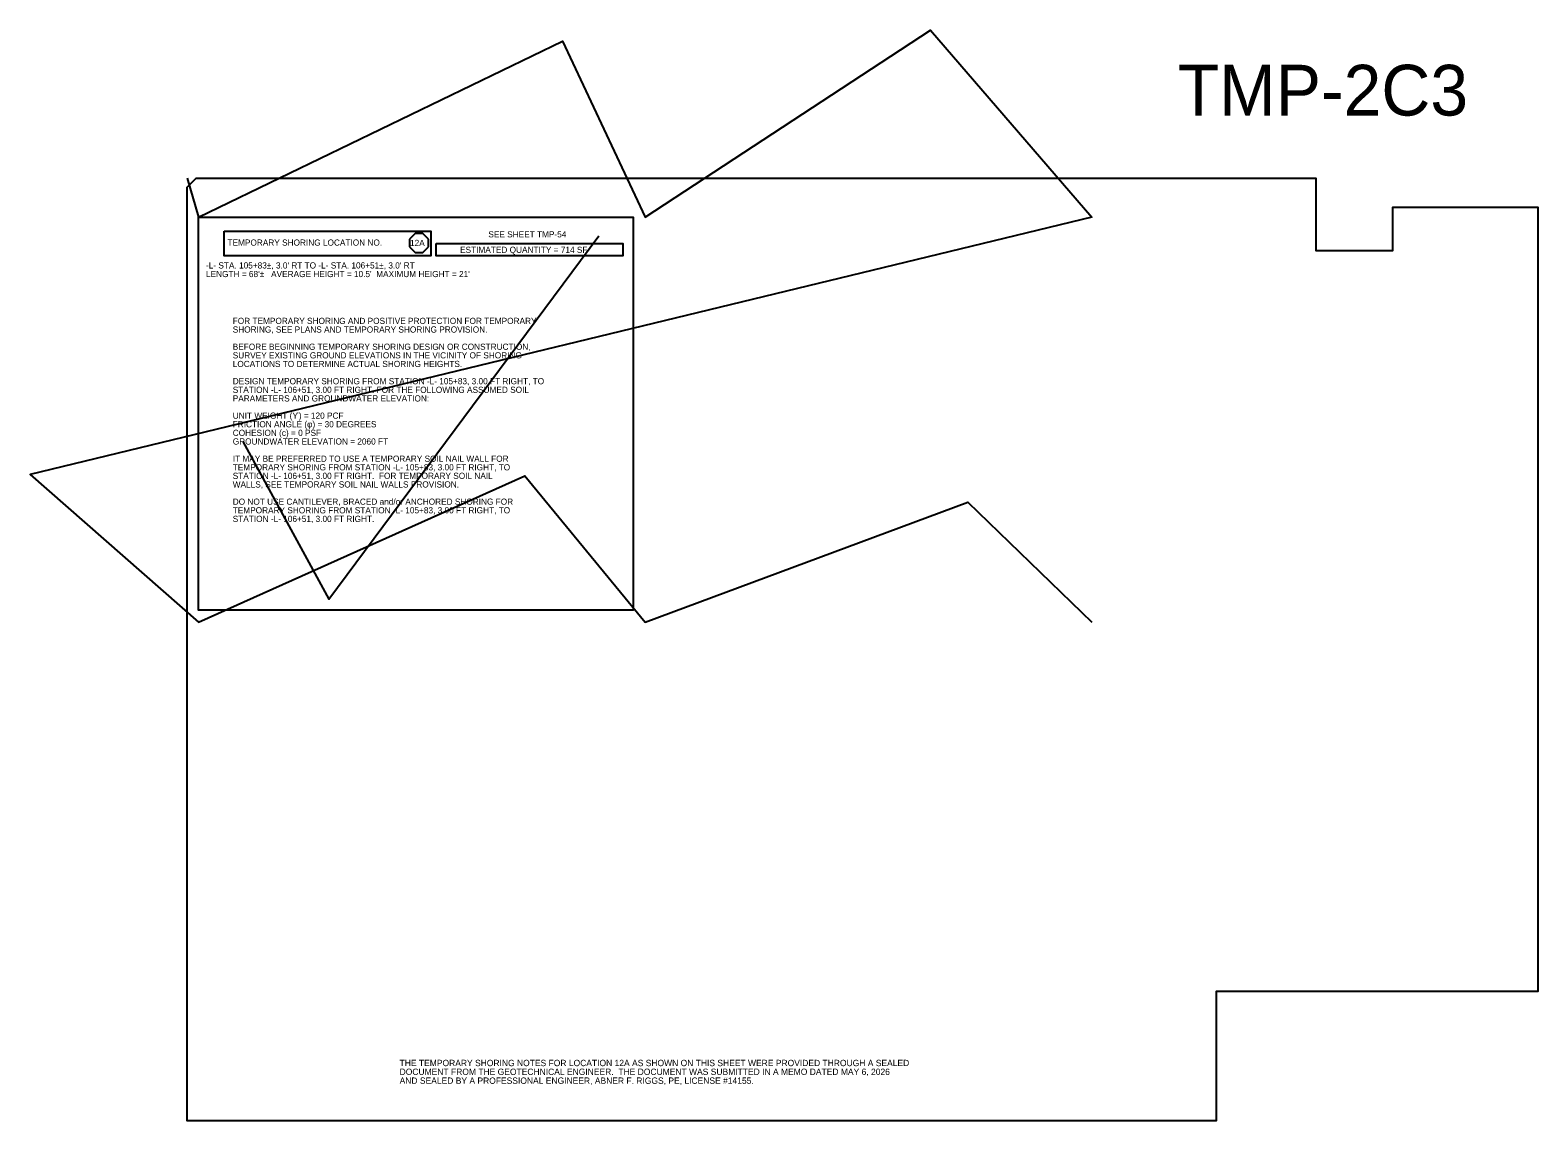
# Model space of a CAD drawing. Extents: x 2487012 to 2497594, y 369516 to 371986.
# Drawn here: x 2495931 to 2497594, y 370242 to 371445 of the extents above; entities that cross this region are included whole.
import ezdxf

# ---------------------------------------------------------------- set-up
doc = ezdxf.new("R2010")
doc.units = 0
for name, color, linetype in [('Scratch_Level_2', 7, 'Continuous'), ('Scratch_Level_3', 7, 'Continuous'), ('Scratch_Level_6', 7, 'Continuous'), ('TC LABEL TEMP SHORING', 7, 'Continuous'), ('TC SHEET BORDER LINE THIN', 7, 'Continuous'), ('TC SHEET LAYOUT SHAPE', 7, 'Continuous'), ('TC SHEET TEXT', 7, 'Continuous')]:
    doc.layers.add(name, color=color, linetype=linetype)

msp = doc.modelspace()

# ---------------------------------------------------------------- linework, layer by layer
at = {"layer": 'Scratch_Level_2'}
msp.add_lwpolyline([(2496165.7, 370991.6), (2496260.7, 370817.8), (2496558.3, 371218.6)], dxfattribs=at)
at = {"layer": 'Scratch_Level_3'}
msp.add_line((2496104.4, 371282.3), (2496104.4, 371282.3), dxfattribs=at)
at = {"layer": 'Scratch_Level_6'}
msp.add_lwpolyline([(2496104.4, 371282.3), (2496116.7, 371239.1), (2496518.3, 371433.4), (2496609.6, 371239.1), (2496924.4, 371445.4), (2497102.5, 371239.1), (2495931.1, 370955.2), (2496116.7, 370792.3), (2496477, 370953.9), (2496609.6, 370792.3), (2496965.7, 370924.6), (2497102.5, 370792.3)], dxfattribs=at)
at = {"layer": 'TC LABEL TEMP SHORING'}
for p, q in [((2496355.7, 371221.2), (2496349.6, 371215)), ((2496364.3, 371221.2), (2496355.7, 371221.2)), ((2496370.4, 371215), (2496364.3, 371221.2)), ((2496349.6, 371215), (2496349.6, 371206.3)), ((2496349.6, 371206.3), (2496355.7, 371200.1)), ((2496364.3, 371200.1), (2496370.4, 371206.3)), ((2496370.4, 371206.3), (2496370.4, 371215)), ((2496355.7, 371200.1), (2496364.3, 371200.1))]:
    msp.add_line(p, q, dxfattribs=at)
at = {"layer": 'TC SHEET BORDER LINE THIN'}
for points in [[(2496116.7, 371239.1), (2496596.2, 371239.1), (2496596.2, 370805.5), (2496116.7, 370805.5)], [(2496145.2, 371223.5), (2496373.3, 371223.5), (2496373.3, 371196.3), (2496145.2, 371196.3)], [(2496379, 371209.9), (2496584.8, 371209.9), (2496584.8, 371196.3), (2496379, 371196.3)]]:
    msp.add_lwpolyline(points, close=True, dxfattribs=at)
at = {"layer": 'TC SHEET LAYOUT SHAPE'}
msp.add_lwpolyline([(2496104.4, 370690.8), (2496104.4, 371000.2), (2496104.4, 371272.3), (2496114.4, 371282.3), (2496557.4, 371282.3), (2497028.4, 371282.3), (2497349.4, 371282.3), (2497349.4, 371202.3), (2497434.4, 371202.3), (2497434.4, 371250.3), (2497594.4, 371250.3), (2497594.4, 370915.3), (2497594.4, 370636.1), (2497594.4, 370384.8), (2497239.4, 370384.8), (2497239.4, 370242.3), (2496866.2, 370242.3), (2496696.8, 370242.3), (2496344, 370242.3), (2496104.4, 370242.3)], close=True, dxfattribs=at)

# ---------------------------------------------------------------- texts
at = {"layer": 'TC LABEL TEMP SHORING'}
msp.add_text('12A', height=6.81, dxfattribs=at).set_placement((2496350.2, 371207.3))
at = {"layer": 'TC SHEET BORDER LINE THIN'}
for s, p in [('SHORING, SEE PLANS AND TEMPORARY SHORING PROVISION.', (2496154.6, 371111.8)), ('FOR TEMPORARY SHORING AND POSITIVE PROTECTION FOR TEMPORARY ', (2496154.6, 371121.3)), ('SURVEY EXISTING GROUND ELEVATIONS IN THE VICINITY OF SHORING ', (2496154.6, 371083.3)), ('BEFORE BEGINNING TEMPORARY SHORING DESIGN OR CONSTRUCTION, ', (2496154.6, 371092.8)), ('LOCATIONS TO DETERMINE ACTUAL SHORING HEIGHTS.', (2496154.6, 371073.8)), ('STATION -L- 106+51, 3.00 FT RIGHT. FOR THE FOLLOWING ASSUMED SOIL ', (2496154.6, 371045.3)), ('DESIGN TEMPORARY SHORING FROM STATION -L- 105+83, 3.00 FT RIGHT, TO ', (2496154.6, 371054.8)), ('PARAMETERS AND GROUNDWATER ELEVATION:', (2496154.6, 371035.8)), ('UNIT WEIGHT (ϒ) = 120 PCF', (2496154.6, 371016.8)), ('COHESION (c) = 0 PSF', (2496154.6, 370997.8)), ('FRICTION ANGLE (φ) = 30 DEGREES', (2496154.6, 371007.3)), ('GROUNDWATER ELEVATION = 2060 FT', (2496154.6, 370988.3)), ('IT MAY BE PREFERRED TO USE A TEMPORARY SOIL NAIL WALL FOR', (2496154.6, 370969.3)), ('TEMPORARY SHORING FROM STATION -L- 105+83, 3.00 FT RIGHT, TO', (2496154.6, 370959.8)), ('STATION -L- 106+51, 3.00 FT RIGHT.  FOR TEMPORARY SOIL NAIL', (2496154.6, 370950.4)), ('WALLS, SEE TEMPORARY SOIL NAIL WALLS PROVISION.', (2496154.6, 370940.9)), ('TEMPORARY SHORING FROM STATION -L- 105+83, 3.00 FT RIGHT, TO', (2496154.6, 370912.4)), ('DO NOT USE CANTILEVER, BRACED and/or ANCHORED SHORING FOR', (2496154.6, 370921.9)), ('STATION -L- 106+51, 3.00 FT RIGHT.', (2496154.6, 370902.9))]:
    msp.add_text(s, height=6.814, dxfattribs=at).set_placement(p)
at = {"layer": 'TC SHEET LAYOUT SHAPE'}
msp.add_text('TMP-2C3', height=56, rotation=0.0001, dxfattribs=at).set_placement((2497197.1, 371351.2))
at = {"layer": 'TC SHEET TEXT'}
for s, height, p in [('SEE SHEET TMP-54', 6.814, (2496436.6, 371216.8)), ('TEMPORARY SHORING LOCATION NO.', 6.814, (2496148.8, 371207.7)), ('ESTIMATED QUANTITY = 714 SF', 6.814, (2496405.4, 371199.7)), ("-L- STA. 105+83±, 3.0' RT TO -L- STA. 106+51±, 3.0' RT", 6.814, (2496125.1, 371182.5)), ("LENGTH = 68'±   AVERAGE HEIGHT = 10.5'  MAXIMUM HEIGHT = 21'", 6.814, (2496125.1, 371173)), ('THE TEMPORARY SHORING NOTES FOR LOCATION 12A AS SHOWN ON THIS SHEET WERE PROVIDED THROUGH A SEALED ', 7, (2496338.7, 370302.6)), ('AND SEALED BY A PROFESSIONAL ENGINEER, ABNER F. RIGGS, PE, LICENSE #14155.', 7, (2496338.7, 370283.1)), ('DOCUMENT FROM THE GEOTECHNICAL ENGINEER.  THE DOCUMENT WAS SUBMITTED IN A MEMO DATED MAY 6, 2026 ', 7, (2496338.7, 370292.9))]:
    msp.add_text(s, height=height, dxfattribs=at).set_placement(p)

doc.saveas('drawing.dxf')
